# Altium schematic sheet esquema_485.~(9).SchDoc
size A4
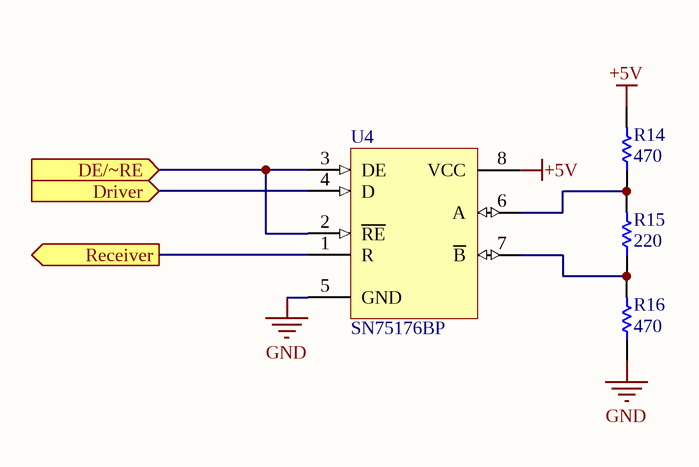
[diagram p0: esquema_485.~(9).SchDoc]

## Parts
R14  value 470  [1005[0402]]  (hidden comment: Carbon 1/8w 5%)
R15  value 220  [1005[0402]]  (hidden comment: Carbon 1/8w 5%)
R16  value 470  [1005[0402]]  (hidden comment: Carbon 1/8w 5%)
U4  SN75176BP  [P008]

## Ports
DE/~RE (in), Driver (in), Receiver (out)

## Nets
+5V: R14.2 U4.8(VCC)
GND: R16.1 U4.5(GND)
DE/~RE: U4.2(~{RE}) U4.3(DE) ; port DE/~RE
Driver: U4.4(D) ; port Driver
Receiver: U4.1(R) ; port Receiver
NetR14_1: R14.1 R15.2 U4.6(A)
NetR15_1: R15.1 R16.2 U4.7(~{B})

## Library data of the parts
R14-R16 = Res Semi: Semiconductor Resistor
U4 = SN75176BP: Differential Bus Transceiver; Note: Receiver Hysteresis of 50mV Typical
